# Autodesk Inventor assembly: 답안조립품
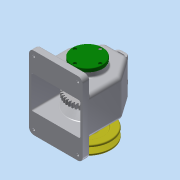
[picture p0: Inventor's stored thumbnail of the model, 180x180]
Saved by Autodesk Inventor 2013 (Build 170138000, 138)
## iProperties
Created: 2016-12
Part Number: 답안조립품
Document SubType Name: Assembly
Designer: narae
Author: narae
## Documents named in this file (14)
- C:\Users\narae\Desktop\461208V1026\답안조립품.iam
- C:\Users\narae\Desktop\461208V1026\V-벨트풀리.ipt
- C:\Users\narae\Desktop\461208V1026\뒤커버.ipt
- C:\Users\narae\Desktop\461208V1026\멈춤나사 - M4x10.ipt
- C:\Users\narae\Desktop\461208V1026\베어링 6203.ipt
- C:\Users\narae\Desktop\461208V1026\본체.ipt
- C:\Users\narae\Desktop\461208V1026\부시.ipt
- C:\Users\narae\Desktop\461208V1026\스퍼기어.ipt
- C:\Users\narae\Desktop\461208V1026\앞커버.ipt
- C:\Users\narae\Desktop\461208V1026\오일씰 28 40 8.ipt
- C:\Users\narae\Desktop\461208V1026\축.ipt
- C:\Users\narae\Desktop\461208V1026\키 - 5 x 5 x 18.ipt
- C:\Users\narae\Desktop\461208V1026\볼트 M3 x 10.ipt
- C:\Users\narae\Desktop\461208V1026\키 - 6 x 6 x 22.ipt
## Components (3 placed, 2 different names)
1. ISO 4762 M3 x 10:1
2. ISO 4762 M3 x 10:2
3. V-벨트풀리:1
